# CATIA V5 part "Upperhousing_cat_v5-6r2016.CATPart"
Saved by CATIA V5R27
Part number: Upperhousing
Bounding box of the stored display mesh (mm): x -40 to 40, y -139 to 75, z 0 to 100
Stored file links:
  E:\_Deepak\2017_Deepak\CATIA\Resources\Tutorial Files\Tutorials\c12_catia_v5_6r2015_tut\c12Tut1\Upperhousing_cat_v5-6r2016.CATPart
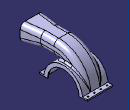
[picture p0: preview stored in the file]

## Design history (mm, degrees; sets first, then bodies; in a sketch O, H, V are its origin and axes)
Set1 "Open_body.1"
  Plane1: type Offset, RefPlane face of Rib1, Offset 57.5, reversed
  Plane2: type Normal, Curve Sketch3, RefPoint Sketch3.P4, Ratio 0
Body1 (main body)
  Sketch1 on yz-plane, origin (0, 0, 0), H (0, 1, 0), V (0, 0, 1)
    arc A1 centre (0, 0) radius 60 from (60, 0) to (-60, 0) ccw
    line L1 (-60, 0) -> (60, 0)
    point P1 (-60, 0)
    radius A1 = 60
    coincidence: P1 H
    horizontal: L1 H
  Pad1: profile Sketch1, direction (1, 0, 0), length 40, mirrored extent
  Sketch2 on Plane2, origin (0, -81.5, -81.5), H (1, 0, 0), V (0, 0, 1)
    line L1 (-28.75, 139.5) -> (28.75, 139.5)
    line L2 (28.75, 139.5) -> (28.75, 181.5)
    line L3 (28.75, 181.5) -> (-28.75, 181.5)
    line L4 (-28.75, 181.5) -> (-28.75, 139.5)
    reference projected point E1 (0, 181.5) from Sketch3.P4
    length L1 = 57.5
    distance L2 V = 28.75
    distance L3 L1 = 42
    horizontal: L1 H, L3 H
    vertical: L2 V, L4 V
    coincidence: L3 E1
  Sketch3 on yz-plane, origin (0, 0, 0), H (0, 1, 0), V (0, 0, 1)
    arc A1 centre (-40, 0) radius 100 from (60, 0) to (-40, 100) ccw
    point P1 (-40, 0)
    point P2 (60, 0)
    line L1 (-81.5, 100) -> (-40, 100)
    point P4 (-81.5, 100)
    point P5 (60, 0)
    radius A1 = 100
    distance P4 V = 81.5
    coincidence: P2 H, P1 H, P5 P2
    horizontal: L1 H
    tangency: L1 A1
  Rib1: profile Sketch2, centre curve Sketch3
  Loft1: solid, Sections (Sketch7; Sketch8)
  Fillet1: radius 15, on edge [face of Rib1 | face of Rib1] (x4); edge [face of Loft1 | face of Loft1] (x2); edge [face of Loft1 | face of Rib1]; edge [face of Rib1 | face of Loft1]
  Fillet2: radius 5, on edge [face of Rib1 | face of Pad1 from Sketch1.A1]
  Shell1: ExtOffset 0, Face (face; face), IntOffset 2.5
  Sketch4 on face of Pad1, origin (40, 0, 0), H (0, 1, 0), V (0, 0, 1)
    circle A1 centre (0, 0) radius 49
    circle A2 centre (0, 0) radius 15
    radius A1 = 49
    radius A2 = 15
  MultiPocket1: profile Sketch4, domains (length 203.2; length 25.4)
  Sketch5 on xy-plane, origin (0, 0, 0), H (1, 0, 0), V (0, 1, 0)
    line L1 (40, 75) -> (-40, 75)
    line L2 (-40, 75) -> (-40, 57.5)
    line L3 (-40, 57.5) -> (40, 57.5)
    line L4 (40, 57.5) -> (40, 75)
    reference projected line E1 (40, 60) -> (40, -60) from edge [face of Pad1 from Sketch1.A1 | end face of Pad1]
    reference projected line E2 (-40, 60) -> (-40, -60) from edge [start face of Pad1 | face of Pad1 from Sketch1.A1]
    reference projected line E3 (-13.75, 57.5) -> (13.75, 57.5) from edge [face of Rib1 | face of Shell1]
    distance L1 H = 75
    horizontal: L1 H, L3 H
    vertical: L2 V, L4 V
    coincidence: L4 E1, L2 E2, L3 E3
  Pad2: profile Sketch5, direction (0, 0, 1), length 4
  Mirror1: of Pad2, Sketch5, about zx-plane
  Sketch6 on face of Pad2, origin (0, 0, 4), H (1, 0, 0), V (0, 1, 0)
    circle A1 centre (30, 67.5) radius 2
    point P1 (30, 67.5)
    reference projected line E1 (40, 75) -> (-40, 75) from edge [face of Pad2 from Sketch5.L1 | end face of Pad2]
    reference projected line E2 (40, 57.5) -> (40, 75) from edge [face of Pad2 from Sketch5.L4 | end face of Pad2]
    radius A1 = 2
    distance P1 E1 = 7.5
    distance P1 E2 = 10
  Pocket1: profile Sketch6, direction (0, 0, -1), through (limit type 6)
  RectPattern1: of Pocket1, direction 1 instances 4, spacing 20, along edge of Pad2 reversed, direction 2 instances 2, spacing 135, along edge of Pad1
  Sketch7 on face of Rib1, origin (0, -81.5, 0), H (1, 0, 0), V (0, 0, 1)
  Sketch8 on Plane1, origin (0, -139, 0), H (-1, 0, 0), V (0, 0, 1)
    line L1 (36.25, 100) -> (-36.25, 100)
    line L2 (-36.25, 100) -> (-36.25, 47.5)
    line L3 (-36.25, 47.5) -> (36.25, 47.5)
    line L4 (36.25, 47.5) -> (36.25, 100)
    reference projected line E1 (-28.75, 100) -> (28.75, 100) from Sketch2.L3
    length L2 = 52.5
    length L1 = 72.5
    distance V L2 = 36.25
    horizontal: L1 H, L3 H
    vertical: L2 V, L4 V
    coincidence: L1 E1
